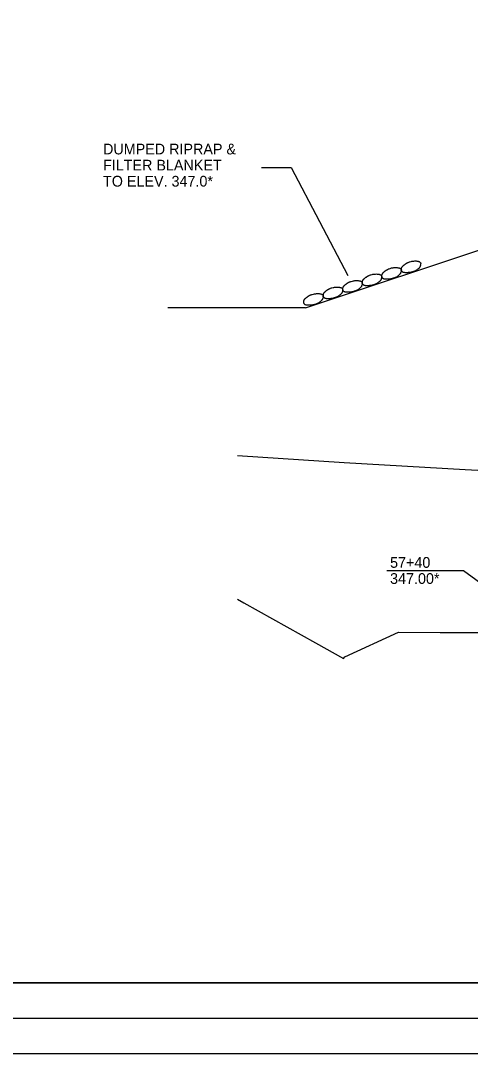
# Model space of a CAD drawing. Extents: x 3575 to 11445, y 9479 to 13278.
# Drawn here: x 6470 to 6722, y 10000 to 10578 of the extents above; entities that cross this region are included whole.
import ezdxf

# ---------------------------------------------------------------- set-up
doc = ezdxf.new("R2010")
doc.units = 0
for name, color, linetype in [('_Drafting 1', 7, 'Continuous'), ('Agg Base Course Text', 7, 'Continuous'), ('Aggregate Base Course', 7, 'Continuous'), ('Default', 7, 'Continuous'), ('R_Dimension', 7, 'Continuous'), ('R_Exist Surface', 7, 'Continuous'), ('R_NoPlot', 7, 'Continuous'), ('R_Vert Alg', 7, 'Continuous'), ('STAMP_PRELIMINARY', 7, 'Continuous')]:
    doc.layers.add(name, color=color, linetype=linetype)

msp = doc.modelspace()

# ---------------------------------------------------------------- linework, layer by layer
at = {"layer": '_Drafting 1'}
msp.add_lwpolyline([(5884.86, 11066.7), (5884.86, 10039.4), (7465.76, 10039.4), (7465.76, 11002.7), (7250.26, 11002.7), (7250.26, 11001.26), (7234.07, 11001.26), (7234.07, 11017.3), (7054.46, 11017.3), (7054.46, 11066.7)], close=True, dxfattribs=at)
at = {"layer": 'Agg Base Course Text'}
msp.add_lwpolyline([(6604.9, 10495.75), (6621.36, 10495.75), (6653.24, 10435.24)], dxfattribs=at)
at = {"layer": 'Aggregate Base Course'}
for points, degree in [([(6683.29, 10438.34), (6683.28, 10438.36), (6683.28, 10438.37), (6683.27, 10438.38), (6683.16, 10438.75), (6683.15, 10439.13), (6683.27, 10439.52), (6683.4, 10439.92), (6683.63, 10440.21), (6683.9, 10440.49), (6684.13, 10440.73), (6684.36, 10440.96), (6684.63, 10441.16), (6685, 10441.44), (6685.38, 10441.71), (6685.78, 10441.97), (6686.02, 10442.13), (6686.27, 10442.28), (6686.53, 10442.41), (6686.91, 10442.6), (6687.31, 10442.75), (6687.71, 10442.85)], 3), ([(6687.71, 10442.85), (6687.76, 10442.86), (6687.8, 10442.88), (6687.84, 10442.89)], 2), ([(6687.84, 10442.89), (6688.46, 10443.11), (6689.12, 10443.23), (6689.79, 10443.31), (6690.61, 10443.41), (6691.39, 10443.41), (6692.23, 10443.26), (6692.78, 10443.17), (6693.27, 10442.96), (6693.69, 10442.57), (6693.87, 10442.4), (6693.98, 10442.2), (6694.08, 10441.98), (6694.08, 10441.97), (6694.09, 10441.96), (6694.09, 10441.94)], 3), ([(6672.36, 10434.7), (6672.36, 10434.71), (6672.35, 10434.73), (6672.35, 10434.74), (6672.23, 10435.1), (6672.22, 10435.48), (6672.35, 10435.88), (6672.47, 10436.28), (6672.7, 10436.57), (6672.97, 10436.85), (6673.2, 10437.09), (6673.43, 10437.32), (6673.7, 10437.52), (6674.07, 10437.8), (6674.45, 10438.07), (6674.85, 10438.33), (6675.1, 10438.49), (6675.34, 10438.63), (6675.6, 10438.77), (6675.98, 10438.96), (6676.38, 10439.11), (6676.79, 10439.21)], 3), ([(6676.79, 10439.21), (6676.83, 10439.22), (6676.87, 10439.24), (6676.91, 10439.25)], 2), ([(6676.91, 10439.25), (6677.54, 10439.47), (6678.19, 10439.58), (6678.86, 10439.66), (6679.68, 10439.76), (6680.46, 10439.76), (6681.3, 10439.62), (6681.85, 10439.53), (6682.34, 10439.32), (6682.76, 10438.92), (6682.94, 10438.75), (6683.06, 10438.56), (6683.15, 10438.34), (6683.15, 10438.33), (6683.16, 10438.31), (6683.16, 10438.3)], 3), ([(6682.9, 10438.21), (6682.92, 10438.17), (6682.93, 10438.13), (6682.95, 10438.08), (6683.08, 10437.65), (6682.93, 10437.18), (6682.73, 10436.73), (6682.61, 10436.45), (6682.46, 10436.23), (6682.26, 10436.01), (6681.92, 10435.62), (6681.56, 10435.27), (6681.14, 10434.97), (6680.6, 10434.57), (6680.05, 10434.2), (6679.43, 10433.97), (6679.17, 10433.87), (6678.9, 10433.78), (6678.62, 10433.7)], 3), ([(6689.55, 10437.34), (6689.49, 10437.33), (6689.44, 10437.31), (6689.38, 10437.29), (6688.91, 10437.13), (6688.42, 10437.02), (6687.93, 10436.95), (6687.4, 10436.87), (6686.87, 10436.86), (6686.34, 10436.84), (6685.88, 10436.82), (6685.43, 10436.82), (6684.97, 10436.86), (6684.45, 10436.9), (6683.97, 10437.11), (6683.57, 10437.49), (6683.37, 10437.68), (6683.24, 10437.91), (6683.16, 10438.16), (6683.15, 10438.2), (6683.13, 10438.24), (6683.12, 10438.28)], 3), ([(6693.83, 10441.86), (6693.85, 10441.81), (6693.86, 10441.77), (6693.88, 10441.73), (6694, 10441.29), (6693.85, 10440.82), (6693.66, 10440.38), (6693.54, 10440.09), (6693.39, 10439.87), (6693.19, 10439.65), (6692.84, 10439.26), (6692.49, 10438.92), (6692.07, 10438.61), (6691.53, 10438.22), (6690.98, 10437.85), (6690.36, 10437.61), (6690.09, 10437.51), (6689.82, 10437.42), (6689.55, 10437.34)], 3), ([(6650.5, 10427.41), (6650.5, 10427.43), (6650.49, 10427.44), (6650.49, 10427.45), (6650.38, 10427.82), (6650.36, 10428.2), (6650.49, 10428.59), (6650.62, 10428.99), (6650.84, 10429.28), (6651.11, 10429.56), (6651.35, 10429.8), (6651.58, 10430.03), (6651.84, 10430.23), (6652.22, 10430.51), (6652.6, 10430.78), (6652.99, 10431.04), (6653.24, 10431.2), (6653.49, 10431.35), (6653.75, 10431.48), (6654.12, 10431.68), (6654.52, 10431.83), (6654.93, 10431.92)], 3), ([(6654.93, 10431.92), (6654.97, 10431.93), (6655.01, 10431.95), (6655.06, 10431.97)], 2), ([(6655.06, 10431.97), (6655.68, 10432.18), (6656.34, 10432.3), (6657.01, 10432.38), (6657.82, 10432.48), (6658.6, 10432.48), (6659.44, 10432.34), (6660, 10432.24), (6660.48, 10432.04), (6660.9, 10431.64), (6661.09, 10431.47), (6661.2, 10431.27), (6661.29, 10431.05), (6661.29, 10431.04), (6661.3, 10431.03), (6661.3, 10431.01)], 3), ([(6661.05, 10430.93), (6661.06, 10430.88), (6661.08, 10430.84), (6661.09, 10430.8), (6661.22, 10430.36), (6661.07, 10429.89), (6660.88, 10429.45), (6660.75, 10429.16), (6660.6, 10428.94), (6660.41, 10428.72), (6660.06, 10428.33), (6659.7, 10427.99), (6659.28, 10427.68), (6658.74, 10427.29), (6658.19, 10426.92), (6657.57, 10426.69), (6657.31, 10426.59), (6657.04, 10426.49), (6656.76, 10426.42)], 3), ([(6667.69, 10430.06), (6667.64, 10430.04), (6667.58, 10430.02), (6667.52, 10430), (6667.05, 10429.84), (6666.57, 10429.73), (6666.07, 10429.66), (6665.54, 10429.58), (6665.01, 10429.58), (6664.48, 10429.55), (6664.02, 10429.54), (6663.57, 10429.54), (6663.11, 10429.57), (6662.59, 10429.62), (6662.11, 10429.82), (6661.72, 10430.2), (6661.51, 10430.4), (6661.39, 10430.62), (6661.3, 10430.87), (6661.29, 10430.91), (6661.27, 10430.96), (6661.26, 10431)], 3), ([(6661.43, 10431.05), (6661.43, 10431.07), (6661.42, 10431.08), (6661.42, 10431.1), (6661.3, 10431.46), (6661.29, 10431.84), (6661.42, 10432.24), (6661.54, 10432.64), (6661.77, 10432.92), (6662.04, 10433.2), (6662.27, 10433.44), (6662.5, 10433.67), (6662.77, 10433.87), (6663.14, 10434.16), (6663.53, 10434.43), (6663.92, 10434.68), (6664.17, 10434.84), (6664.42, 10434.99), (6664.68, 10435.12), (6665.05, 10435.32), (6665.45, 10435.47), (6665.86, 10435.57)], 3), ([(6665.86, 10435.57), (6665.9, 10435.58), (6665.94, 10435.6), (6665.98, 10435.61)], 2), ([(6665.98, 10435.61), (6666.61, 10435.83), (6667.27, 10435.94), (6667.93, 10436.02), (6668.75, 10436.12), (6669.53, 10436.12), (6670.37, 10435.98), (6670.92, 10435.88), (6671.41, 10435.68), (6671.83, 10435.28), (6672.01, 10435.11), (6672.13, 10434.91), (6672.22, 10434.7), (6672.22, 10434.68), (6672.23, 10434.67), (6672.23, 10434.66)], 3), ([(6671.98, 10434.57), (6671.99, 10434.53), (6672.01, 10434.48), (6672.02, 10434.44), (6672.15, 10434), (6672, 10433.54), (6671.8, 10433.09), (6671.68, 10432.81), (6671.53, 10432.58), (6671.34, 10432.36), (6670.99, 10431.98), (6670.63, 10431.63), (6670.21, 10431.33), (6669.67, 10430.93), (6669.12, 10430.56), (6668.5, 10430.33), (6668.24, 10430.23), (6667.97, 10430.14), (6667.69, 10430.06)], 3), ([(6678.62, 10433.7), (6678.56, 10433.68), (6678.51, 10433.66), (6678.45, 10433.64), (6677.98, 10433.49), (6677.49, 10433.38), (6677, 10433.3), (6676.47, 10433.23), (6675.94, 10433.22), (6675.41, 10433.2), (6674.95, 10433.18), (6674.5, 10433.18), (6674.04, 10433.22), (6673.52, 10433.26), (6673.04, 10433.46), (6672.64, 10433.84), (6672.44, 10434.04), (6672.31, 10434.26), (6672.23, 10434.51), (6672.22, 10434.56), (6672.2, 10434.6), (6672.19, 10434.64)], 3), ([(6633.2, 10424.68), (6633.82, 10424.9), (6634.48, 10425.01), (6635.15, 10425.09), (6635.96, 10425.19), (6636.75, 10425.19), (6637.58, 10425.05), (6638.14, 10424.95), (6638.63, 10424.75), (6639.05, 10424.35), (6639.23, 10424.18), (6639.34, 10423.98), (6639.43, 10423.77), (6639.44, 10423.76), (6639.44, 10423.74), (6639.45, 10423.73)], 3), ([(6639.57, 10423.77), (6639.57, 10423.78), (6639.56, 10423.8), (6639.56, 10423.81), (6639.45, 10424.17), (6639.43, 10424.55), (6639.56, 10424.95), (6639.69, 10425.35), (6639.91, 10425.64), (6640.19, 10425.92), (6640.42, 10426.16), (6640.65, 10426.39), (6640.91, 10426.59), (6641.29, 10426.87), (6641.67, 10427.14), (6642.06, 10427.4), (6642.31, 10427.56), (6642.56, 10427.7), (6642.82, 10427.84), (6643.19, 10428.03), (6643.59, 10428.18), (6644, 10428.28)], 3), ([(6644, 10428.28), (6644.04, 10428.29), (6644.08, 10428.31), (6644.13, 10428.32)], 2), ([(6644.13, 10428.32), (6644.75, 10428.54), (6645.41, 10428.65), (6646.08, 10428.74), (6646.89, 10428.83), (6647.67, 10428.84), (6648.51, 10428.69), (6649.07, 10428.6), (6649.55, 10428.39), (6649.98, 10428), (6650.16, 10427.82), (6650.27, 10427.63), (6650.36, 10427.41), (6650.37, 10427.4), (6650.37, 10427.38), (6650.37, 10427.37)], 3), ([(6650.12, 10427.28), (6650.13, 10427.24), (6650.15, 10427.2), (6650.16, 10427.16), (6650.29, 10426.72), (6650.14, 10426.25), (6649.95, 10425.8), (6649.83, 10425.52), (6649.67, 10425.3), (6649.48, 10425.08), (6649.13, 10424.69), (6648.77, 10424.34), (6648.35, 10424.04), (6647.81, 10423.65), (6647.26, 10423.28), (6646.65, 10423.04), (6646.38, 10422.94), (6646.11, 10422.85), (6645.83, 10422.77)], 3), ([(6656.76, 10426.42), (6656.71, 10426.4), (6656.65, 10426.38), (6656.59, 10426.36), (6656.12, 10426.2), (6655.64, 10426.09), (6655.14, 10426.02), (6654.61, 10425.94), (6654.09, 10425.93), (6653.55, 10425.91), (6653.1, 10425.89), (6652.65, 10425.89), (6652.18, 10425.93), (6651.66, 10425.98), (6651.18, 10426.18), (6650.79, 10426.56), (6650.58, 10426.75), (6650.46, 10426.98), (6650.37, 10427.23), (6650.36, 10427.27), (6650.35, 10427.31), (6650.33, 10427.35)], 3), ([(6634.91, 10419.13), (6634.85, 10419.11), (6634.79, 10419.09), (6634.73, 10419.07), (6634.26, 10418.92), (6633.78, 10418.8), (6633.28, 10418.73), (6632.75, 10418.65), (6632.23, 10418.65), (6631.7, 10418.63), (6631.24, 10418.61), (6630.79, 10418.61), (6630.32, 10418.65), (6629.81, 10418.69), (6629.32, 10418.89), (6628.93, 10419.27), (6628.73, 10419.47), (6628.6, 10419.69), (6628.52, 10419.94), (6628.5, 10419.98), (6628.49, 10420.03), (6628.47, 10420.07)], 3), ([(6628.64, 10420.13), (6628.64, 10420.14), (6628.63, 10420.15), (6628.63, 10420.17), (6628.52, 10420.53), (6628.5, 10420.91), (6628.63, 10421.31), (6628.76, 10421.71), (6628.99, 10421.99), (6629.26, 10422.27), (6629.49, 10422.51), (6629.72, 10422.74), (6629.98, 10422.94), (6630.36, 10423.23), (6630.74, 10423.5), (6631.13, 10423.75), (6631.38, 10423.91), (6631.63, 10424.06), (6631.89, 10424.2), (6632.26, 10424.39), (6632.66, 10424.54), (6633.07, 10424.64)], 3), ([(6633.07, 10424.64), (6633.11, 10424.65), (6633.15, 10424.67), (6633.2, 10424.68)], 2), ([(6639.19, 10423.64), (6639.2, 10423.6), (6639.22, 10423.56), (6639.23, 10423.51), (6639.36, 10423.07), (6639.21, 10422.61), (6639.02, 10422.16), (6638.9, 10421.88), (6638.75, 10421.65), (6638.55, 10421.44), (6638.2, 10421.05), (6637.84, 10420.7), (6637.42, 10420.4), (6636.88, 10420), (6636.33, 10419.63), (6635.72, 10419.4), (6635.45, 10419.3), (6635.18, 10419.21), (6634.91, 10419.13)], 3), ([(6645.83, 10422.77), (6645.78, 10422.75), (6645.72, 10422.73), (6645.66, 10422.72), (6645.19, 10422.56), (6644.71, 10422.45), (6644.21, 10422.37), (6643.68, 10422.3), (6643.16, 10422.29), (6642.63, 10422.27), (6642.17, 10422.25), (6641.72, 10422.25), (6641.25, 10422.29), (6640.74, 10422.33), (6640.25, 10422.53), (6639.86, 10422.92), (6639.66, 10423.11), (6639.53, 10423.34), (6639.45, 10423.58), (6639.43, 10423.63), (6639.42, 10423.67), (6639.4, 10423.71)], 3)]:
    msp.add_open_spline(points, degree=degree, dxfattribs=at)
at = {"layer": 'Default'}
for q in [(6844.84, 10488.97), (6552.44, 10417.16)]:
    msp.add_line((6629.4, 10417.16), q, dxfattribs=at)
at = {"layer": 'R_Dimension'}
msp.add_lwpolyline([(6675.07, 10270.2), (6717.94, 10270.2), (6743.44, 10251.5)], dxfattribs=at)
at = {"layer": 'R_Exist Surface'}
msp.add_lwpolyline([(6591.36, 10254.12), (6595.03, 10252.06), (6635.03, 10229.63), (6650.68, 10220.93), (6651.52, 10221.79), (6681.52, 10235.6), (6704.79, 10235.42), (6721.14, 10235.48), (6732.38, 10235.53)], dxfattribs=at)
at = {"layer": 'R_NoPlot'}
msp.add_lwpolyline([(5822.82, 11086.17), (7489.52, 11086.17), (7489.52, 10019.49), (5822.82, 10019.49)], close=True, dxfattribs=at)
at = {"layer": 'R_Vert Alg'}
msp.add_lwpolyline([(6591.36, 10334.56), (6651.14, 10330.67), (6718.85, 10326.72), (6786.55, 10323.25), (6854.26, 10320.23), (6921.97, 10317.68), (6989.68, 10315.59), (7057.39, 10313.97), (7125.1, 10312.82), (7144.47, 10312.62)], dxfattribs=at)
at = {"layer": 'STAMP_PRELIMINARY'}
for p, q in [((7465.76, 10039.4), (5884.86, 10039.4)), ((5728.76, 10000), (7488.76, 10000))]:
    msp.add_line(p, q, dxfattribs=at)

# ---------------------------------------------------------------- texts
at = {"layer": 'Agg Base Course Text'}
for s, p in [('DUMPED RIPRAP &', (6516.14, 10503.03)), ('FILTER BLANKET', (6516.14, 10494.03)), ('TO ELEV. 347.0*', (6516.14, 10485.03))]:
    msp.add_text(s, height=6, dxfattribs=at).set_placement(p)
at = {"layer": 'R_Dimension'}
for s, p in [('57+40', (6676.82, 10271.7)), ('347.00*', (6676.82, 10262.7))]:
    msp.add_text(s, height=6, dxfattribs=at).set_placement(p)

doc.saveas('drawing.dxf')
